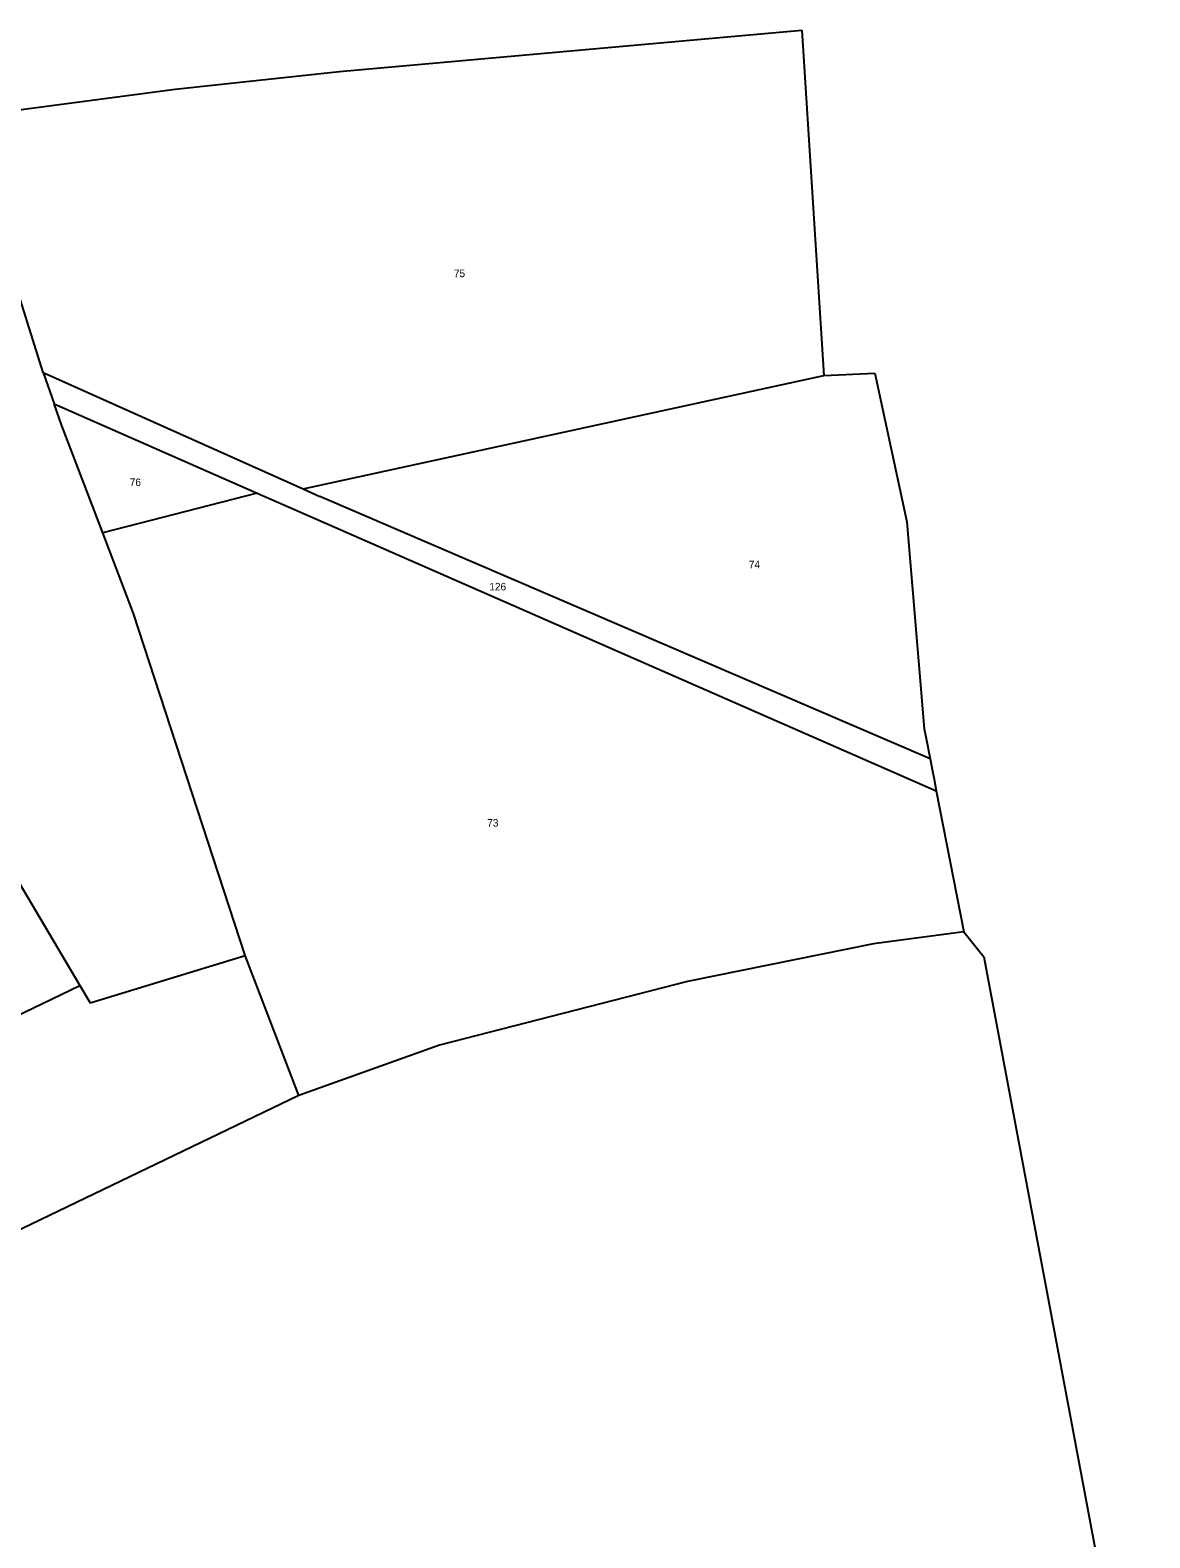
# Model space of a CAD drawing. Extents: x -752343 to -750336, y -1035826 to -1033329.
# Drawn here: x -750613.5 to -750361.2, y -1035442.9 to -1035103.4 of the extents above; entities that cross this region are included whole.
import ezdxf

# ---------------------------------------------------------------- set-up
doc = ezdxf.new("R2010")
doc.units = 0
doc.layers.add('KN_HRANICE', color=7, linetype='Continuous')
doc.layers.add('KN_PARCELY', color=7, linetype='Continuous')

msp = doc.modelspace()

# ---------------------------------------------------------------- linework, layer by layer
at = {"layer": 'KN_HRANICE'}
for p, q in [((-750543.82, -1035112.68), (-750439.65, -1035103.37)), ((-750439.65, -1035103.37), (-750434.66, -1035181.11)), ((-750580.87, -1035116.68), (-750543.82, -1035112.68)), ((-750627.75, -1035122.82), (-750580.87, -1035116.68)), ((-750610.6, -1035180.44), (-750620.53, -1035149.1)), ((-750610.6, -1035180.44), (-750608.12, -1035187.55)), ((-750610.6, -1035180.44), (-750551.99, -1035206.69)), ((-750551.99, -1035206.69), (-750434.66, -1035181.11)), ((-750434.66, -1035181.11), (-750423.17, -1035180.61)), ((-750423.17, -1035180.61), (-750415.94, -1035214.11)), ((-750606.45, -1035192.27), (-750608.12, -1035187.55)), ((-750608.12, -1035187.55), (-750562.36, -1035207.63)), ((-750597.18, -1035216.54), (-750606.45, -1035192.27)), ((-750562.36, -1035207.63), (-750597.18, -1035216.54)), ((-750562.36, -1035207.63), (-750550.34, -1035212.91)), ((-750551.99, -1035206.69), (-750548.24, -1035208.37)), ((-750410.73, -1035267.48), (-750548.24, -1035208.37)), ((-750550.34, -1035212.91), (-750409.34, -1035274.65)), ((-750415.94, -1035214.11), (-750412.04, -1035260.74)), ((-750590.21, -1035234.77), (-750597.18, -1035216.54)), ((-750565.07, -1035311.79), (-750590.21, -1035234.77)), ((-750412.04, -1035260.74), (-750411.69, -1035262.54)), ((-750411.69, -1035262.54), (-750410.73, -1035267.48)), ((-750410.73, -1035267.48), (-750410.19, -1035270.23)), ((-750410.19, -1035270.23), (-750409.84, -1035272.03)), ((-750409.84, -1035272.03), (-750409.34, -1035274.65)), ((-750409.34, -1035274.65), (-750403.15, -1035306.45)), ((-750619.19, -1035290.09), (-750602.3, -1035318.55)), ((-750403.15, -1035306.45), (-750423.47, -1035309.16)), ((-750403.15, -1035306.45), (-750398.6, -1035312.05)), ((-750423.47, -1035309.16), (-750465.41, -1035317.63)), ((-750599.98, -1035322.46), (-750565.07, -1035311.79)), ((-750553.02, -1035343.26), (-750565.07, -1035311.79)), ((-750398.6, -1035312.05), (-750379.9, -1035411.42)), ((-750761.16, -1035394.35), (-750602.3, -1035318.55)), ((-750602.3, -1035318.55), (-750599.98, -1035322.46)), ((-750465.41, -1035317.63), (-750521.26, -1035331.95)), ((-750521.26, -1035331.95), (-750553.02, -1035343.26)), ((-750553.02, -1035343.26), (-750737.45, -1035432.01)), ((-750379.9, -1035411.42), (-750361.2, -1035510.78))]:
    msp.add_line(p, q, dxfattribs=at)

# ---------------------------------------------------------------- texts
at = {"layer": 'KN_PARCELY'}
for s, p in [('75', (-750518.04, -1035159)), ('76', (-750591.09, -1035206.04)), ('74', (-750451.57, -1035224.55)), ('126', (-750510.06, -1035229.55)), ('73', (-750510.53, -1035282.74))]:
    msp.add_text(s, height=1.7, dxfattribs=at).set_placement(p)

doc.saveas('drawing.dxf')
